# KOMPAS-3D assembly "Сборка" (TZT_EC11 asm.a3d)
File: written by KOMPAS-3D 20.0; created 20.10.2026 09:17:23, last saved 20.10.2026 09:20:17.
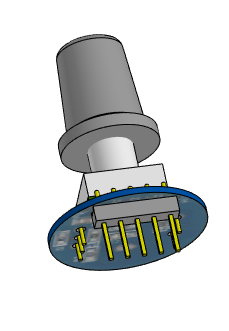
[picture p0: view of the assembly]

Document properties: Полное имя файла: D:\RicWork\Project-EPS32\box_compas\переключатели и кнопки\TZT_EC11 asm.a3d

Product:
- Part/product: Сборка
    Масса: 0.0191636
  - Component [detail]: Деталь  | Масса: 0.0140072; source file: ..\ручки\ручка.m3d
  - Component [detail]: Деталь  | Материал: Фторопласт-4  ГОСТ 10007-80 Е (density 2200 kg/m3); Масса: 0.000956379; source file: TZT_EC11 pcb.m3d.bak
  - Component [detail]: Деталь  | Материал: Фторопласт-4  ГОСТ 10007-80 Е (density 2200 kg/m3); Масса: 0.00354823; source file: EC11 S.m3d
  - Component [detail]: Деталь  | Масса: 0.000651758; source file: ..\разъемы\pls_5.m3d

Referenced files in D:\RicWork\Project-EPS32\box_compas\переключатели и кнопки\: TZT_EC11 pcb.m3d.bak, EC11 S.m3d
Referenced files in D:\RicWork\Project-EPS32\box_compas\разъемы\: pls_5.m3d
Referenced files in D:\RicWork\Project-EPS32\box_compas\ручки\: ручка.m3d
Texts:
  TZT_EC11 pcb.m3d.bak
